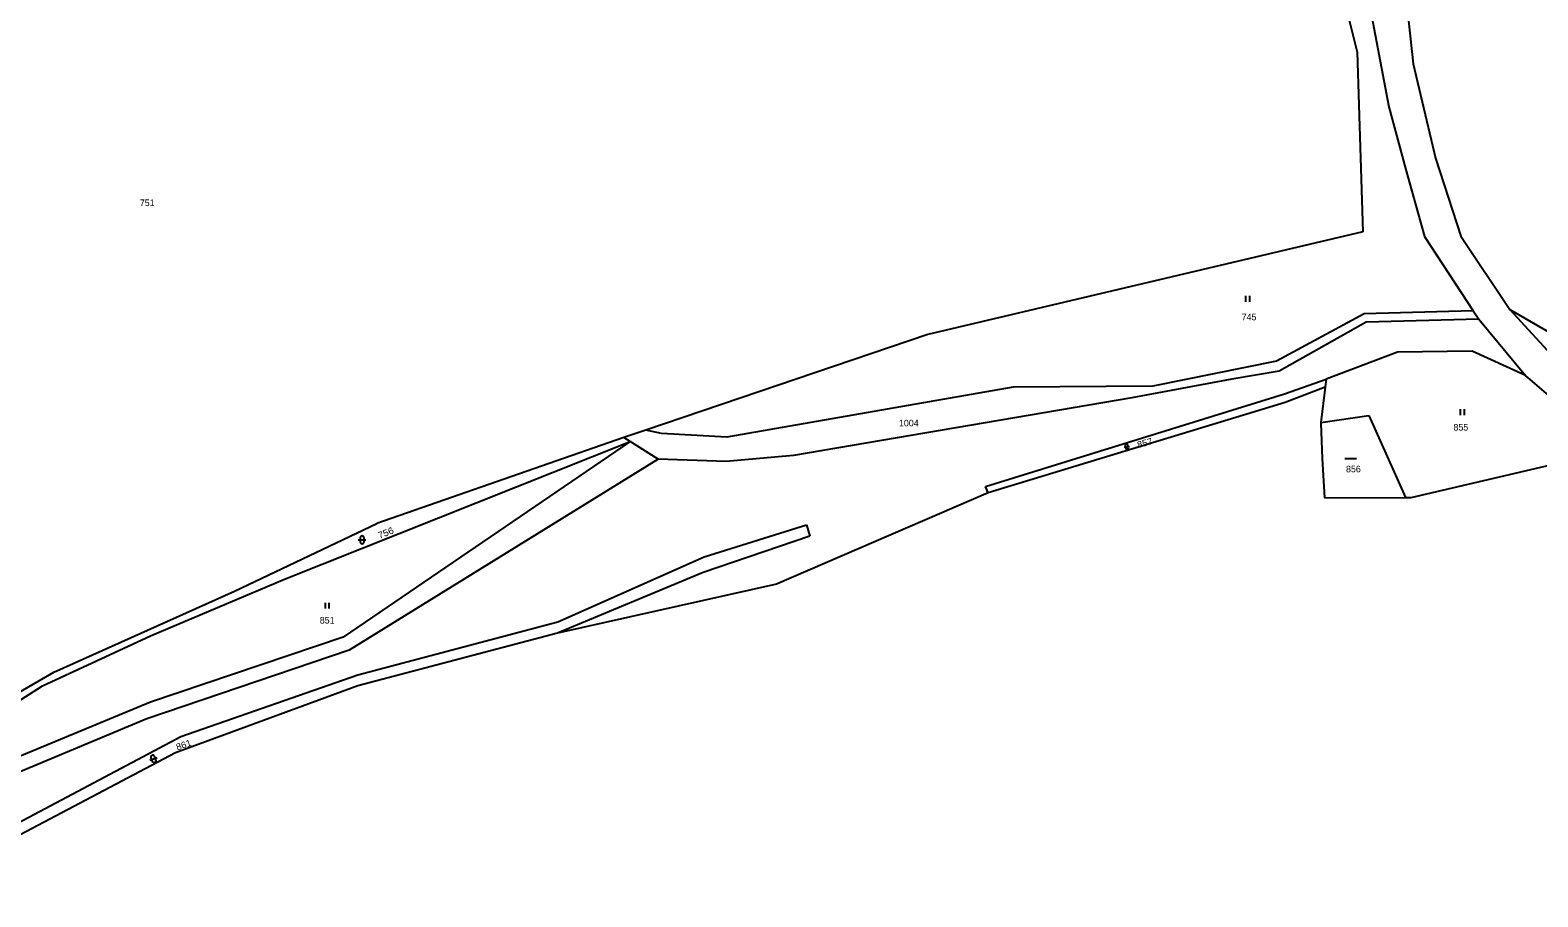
# Model space of a CAD drawing. Extents: x -744132 to -742433, y -984679 to -982287.
# Drawn here: x -743440.4 to -743052.8, y -982795.5 to -982572.6 of the extents above; entities that cross this region are included whole.
import ezdxf

# ---------------------------------------------------------------- set-up
doc = ezdxf.new("R2010")
doc.units = 0
doc.header["$LTSCALE"] = 0.68
doc.layers.add('1', color=7, linetype='Continuous', lineweight=25)
doc.layers.add('3', color=7, linetype='Continuous', lineweight=25)
doc.layers.add('2', color=7, linetype='Continuous')

msp = doc.modelspace()

# ---------------------------------------------------------------- linework, layer by layer
at = {"layer": '1'}
for p, q in [((-743116.14, -982511.59), (-743099.24, -982578.2)), ((-743097.04, -982560.9), (-743091.09, -982592.29)), ((-743087.31, -982558.84), (-743084.83, -982581.2)), ((-743099.24, -982578.2), (-743097.77, -982624.44)), ((-743084.83, -982581.2), (-743079.15, -982605.48)), ((-743091.09, -982592.29), (-743086.8, -982608.12)), ((-743086.8, -982608.12), (-743081.94, -982625.65)), ((-743079.15, -982605.48), (-743072.6, -982625.56)), ((-743097.77, -982624.44), (-743209.66, -982650.81)), ((-743081.94, -982625.65), (-743069.4, -982644.76)), ((-743072.6, -982625.56), (-743060.05, -982644.41)), ((-743097.46, -982645.56), (-743119.98, -982657.68)), ((-743096.91, -982647.64), (-743119.35, -982660.26)), ((-743069.4, -982644.76), (-743097.46, -982645.56)), ((-743067.95, -982646.93), (-743096.91, -982647.64)), ((-743069.4, -982644.76), (-743067.95, -982646.93)), ((-743067.95, -982646.93), (-743056.03, -982661.36)), ((-743060.05, -982644.41), (-743017.91, -982668.68)), ((-743060.05, -982644.41), (-743047.6, -982657.96)), ((-743209.66, -982650.81), (-743282.11, -982675.4)), ((-743088.9, -982655.39), (-743107.27, -982662.32)), ((-743069.67, -982655.15), (-743088.9, -982655.39)), ((-743056.03, -982661.36), (-743069.67, -982655.15)), ((-743119.98, -982657.68), (-743151.8, -982664.12)), ((-743131.5, -982662.36), (-743157.21, -982667.1)), ((-743119.35, -982660.26), (-743131.5, -982662.36)), ((-743117.97, -982666.09), (-743107.27, -982662.32)), ((-743107.27, -982662.32), (-743107.51, -982664.41)), ((-743040.93, -982674.39), (-743056.03, -982661.36)), ((-743187.73, -982664.36), (-743261.27, -982677.27)), ((-743157.21, -982667.1), (-743244.19, -982681.98)), ((-743194.82, -982689.96), (-743117.97, -982666.09)), ((-743151.8, -982664.12), (-743187.73, -982664.36)), ((-743107.51, -982664.41), (-743117.73, -982668.34)), ((-743107.51, -982664.41), (-743108.58, -982673.51)), ((-743117.73, -982668.34), (-743194.15, -982691.52)), ((-743108.58, -982673.51), (-743108.6, -982673.65)), ((-743108.6, -982673.65), (-743108.24, -982682.73)), ((-743108.58, -982673.51), (-743096.3, -982671.7)), ((-743096.3, -982671.7), (-743086.8, -982692.72)), ((-743374.97, -982713.78), (-743286.12, -982678.39)), ((-743286.12, -982678.39), (-743359.96, -982728.7)), ((-743287.73, -982677.31), (-743351.3, -982699.47)), ((-743282.11, -982675.4), (-743287.73, -982677.31)), ((-743286.12, -982678.39), (-743287.73, -982677.31)), ((-743278.98, -982682.88), (-743286.12, -982678.39)), ((-743278.05, -982676.34), (-743282.11, -982675.4)), ((-743261.27, -982677.27), (-743278.05, -982676.34)), ((-743244.19, -982681.98), (-743261.48, -982683.5)), ((-743085.35, -982692.77), (-743038.38, -982681.7)), ((-743278.98, -982682.88), (-743358.4, -982732.02)), ((-743261.48, -982683.5), (-743278.98, -982682.88)), ((-743108.24, -982682.73), (-743107.69, -982692.84)), ((-743194.15, -982691.52), (-743194.82, -982689.96)), ((-743194.15, -982691.52), (-743248.56, -982715.09)), ((-743107.69, -982692.84), (-743086.8, -982692.72)), ((-743086.8, -982692.72), (-743085.35, -982692.77)), ((-743387.84, -982716.87), (-743351.3, -982699.47)), ((-743267.1, -982708.05), (-743240.79, -982699.77)), ((-743240.79, -982699.77), (-743239.94, -982702.69)), ((-743239.94, -982702.69), (-743267.34, -982712.07)), ((-743304.73, -982724.73), (-743267.1, -982708.05)), ((-743267.34, -982712.07), (-743304.84, -982727.66)), ((-743434.31, -982737.66), (-743387.84, -982716.87)), ((-743409.41, -982728.31), (-743374.97, -982713.78)), ((-743248.56, -982715.09), (-743304.84, -982727.66)), ((-743356.14, -982738.35), (-743304.73, -982724.73)), ((-743437.23, -982741.22), (-743409.41, -982728.31)), ((-743359.96, -982728.7), (-743409.47, -982745.36)), ((-743304.84, -982727.66), (-743356.18, -982741.17)), ((-743358.4, -982732.02), (-743410.39, -982749.69)), ((-743444.9, -982743.86), (-743434.31, -982737.66)), ((-743401.62, -982754.22), (-743356.14, -982738.35)), ((-743501.13, -982782.2), (-743437.23, -982741.22)), ((-743356.18, -982741.17), (-743403.06, -982758.47)), ((-743409.47, -982745.36), (-743453.51, -982763.67)), ((-743410.39, -982749.69), (-743497.45, -982786.05)), ((-743475.99, -982793.71), (-743401.62, -982754.22)), ((-743403.06, -982758.47), (-743473.35, -982795.48))]:
    msp.add_line(p, q, dxfattribs=at)
at = {"layer": '3'}
for p, q in [((-743127.881, -982642.43), (-743127.881, -982640.93)), ((-743126.88, -982642.43), (-743126.88, -982640.93)), ((-743072.671, -982671.56), (-743072.671, -982670.06)), ((-743071.67, -982671.56), (-743071.67, -982670.06)), ((-743159.172, -982679.843), (-743157.791, -982679.6)), ((-743158.887, -982679.437), (-743158.766, -982680.127)), ((-743158.075, -982680.006), (-743158.197, -982679.315)), ((-743102.398, -982682.7), (-743099.398, -982682.7)), ((-743356.051, -982703.661), (-743354.049, -982703.661)), ((-743355.551, -982703.161), (-743355.551, -982704.162)), ((-743354.549, -982704.162), (-743354.549, -982703.161)), ((-743364.481, -982721.35), (-743364.481, -982719.85)), ((-743363.48, -982721.35), (-743363.48, -982719.85)), ((-743409.623, -982760.336), (-743407.753, -982759.619)), ((-743409.335, -982759.69), (-743408.976, -982760.624)), ((-743408.041, -982760.265), (-743408.4, -982759.331))]:
    msp.add_line(p, q, dxfattribs=at)
for centre, radius, start, end in [((-743158.5422, -982679.3766), 0.35, 10, 190), ((-743158.4207, -982680.0659), 0.35, 190, 9.98789), ((-743355.05, -982703.1609), 0.5, 0, 180), ((-743355.05, -982704.1609), 0.5, 180, 359.98789), ((-743408.8672, -982759.5105), 0.5, 21, 201), ((-743408.5089, -982760.4441), 0.5, 201, 20.98789)]:
    msp.add_arc(centre, radius, start, end, dxfattribs=at)

# ---------------------------------------------------------------- texts
at = {"layer": '2'}
for s, p in [('751', (-743412.19, -982617.805)), ('745', (-743128.94, -982647.175)), ('1004', (-743217.05, -982674.475)), ('855', (-743074.5, -982675.545)), ('856', (-743102.12, -982686.295)), ('851', (-743365.92, -982725.185))]:
    msp.add_text(s, height=1.7, dxfattribs=at).set_placement(p)
for s, rotation, width, p in [('857', 14, 1.05, (-743155.587, -982680.042)), ('756', 22, 1.1, (-743350.58, -982703.424)), ('861', 19, 1.05, (-743402.521, -982757.841))]:
    msp.add_text(s, height=1.7, rotation=rotation, dxfattribs=dict(at, width=width)).set_placement(p)

doc.saveas('drawing.dxf')
